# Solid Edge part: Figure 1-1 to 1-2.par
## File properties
Author: CADCIM
Template: normal.par
Last saved by: Ashutosh-CADCIM
Revision: 20
Application: Solid Edge
Accuracy: 0.99
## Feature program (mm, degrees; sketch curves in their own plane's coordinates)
sketch for "unnamed Protrusion 1" plane through (0, 0, 0) normal (0, 0, 1) x-axis (1, 0, 0)
  line (-63.0032, 49) -> (-56, -71)
  line (-56, -71) -> (56, -71)
  line (56, -71) -> (63.0032, 49)
  line (63.0032, 49) -> (0, 54)
  line (0, 54) -> (-63.0032, 49)
  dimension (linear) = 56
  dimension (linear) = 56
extrude "unnamed Protrusion 1" add finite 4 along +normal
fillet "Round_1" radius 15
sketch for "ExtrudedProtrusion_3" plane through (0, -8.5, 0) normal (0, 0, -1) x-axis (-1, 0, 0)
extrude "ExtrudedProtrusion_3" add finite 12 along -normal
pattern "unnamed Pattern 1" of "ExtrudedProtrusion_3"
pattern "unnamed Pattern 2"
sketch for "unnamed Protrusion 2" plane through (-1.0316, 2.3101, 4) normal (0, 0, 1) x-axis (-1, 0, 0)
extrude "unnamed Protrusion 2" add finite 5 along +normal
sketch for "Hole_22" plane through (40.9331, -54.9887, 12) normal (0, 0, 1) x-axis (1, 0, 0)
  hole centre (-0.4331, -0.0113) bore radius 4.5
hole "Hole_22" diameter 9 through  CounterBoreDepth = 5 mm
pattern "unnamed Pattern 3" of "Hole_22"
hole "unnamed Hole 1" through
hole "unnamed Hole 2" through
hole "unnamed Hole 3" through
sketch for "Hole_29" plane through (-1.0316, -6.1899, 9) normal (0, 0, 1) x-axis (1, 0, 0)
  hole centre (0, 0) bore radius 11
hole "Hole_29" diameter 22 through
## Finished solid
Body 1: solid body, 34 faces, 55 edges, 18 vertices.
  Faces by surface: cylinder 18, plane 16
  Edges by curve: circle 36, line 19
Bounding box of the edges (mm): 124.346 x 125.000 x 12.000, from (-62.1729, -71, 0) to (62.1729, 54, 12).
Cylindrical faces by radius (mm): R4.5 x4, R7.5 x4, R10.7006 x4, R11 x1, R15 x4, R20 x1
Planar faces by outward normal: +z 10, -y 1, -z 1, oblique 4
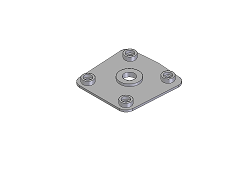
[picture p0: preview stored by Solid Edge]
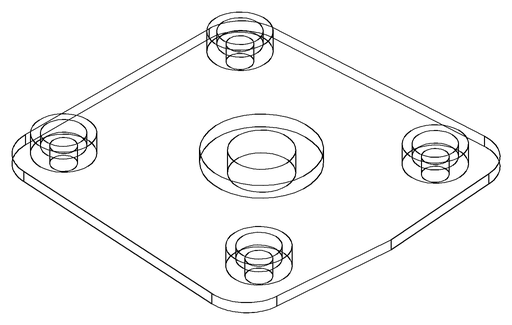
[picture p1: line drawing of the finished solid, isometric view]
